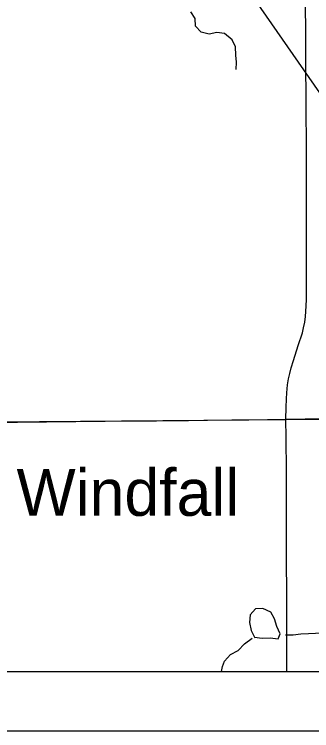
# Model space of a CAD drawing. Extents: x 0 to 34, y 0 to 22.
# Drawn here: x 2.893 to 3.395, y 14 to 15.21 of the extents above; entities that cross this region are included whole.
import ezdxf

# ---------------------------------------------------------------- set-up
doc = ezdxf.new("R2010")
doc.units = 0
for name, color, linetype in [('GM_X_Corporation', 7, 'Continuous'), ('GM_X_Minor_Lake', 7, 'Continuous'), ('GM_X_Minor_River', 7, 'Continuous'), ('GM_X_State_Route', 7, 'Continuous'), ('GM_X_Township_Road', 7, 'Continuous'), ('GM_X_Unincorporated_Text', 7, 'Continuous'), ('SH_Data', 7, 'Continuous'), ('SH_Text', 7, 'Continuous')]:
    doc.layers.add(name, color=color, linetype=linetype)

msp = doc.modelspace()

# ---------------------------------------------------------------- linework, layer by layer
at = {"layer": 'GM_X_Corporation'}
for points in [[(2.1, 20.9), (2.1, 14.1), (7.9734, 14.1), (7.9726, 14.5453), (7.9765, 15.2637), (7.9792, 15.5481), (7.979, 15.5988), (7.9808, 15.7192), (7.9807, 15.9078), (7.9821, 16.2487), (7.9825, 16.3395), (7.9818, 16.3982), (7.9825, 16.6077), (7.9838, 16.7968), (7.9877, 17.3871), (7.9891, 17.5498), (7.991, 17.7727), (7.9901, 18.1613)], [(3.735, 14.5275), (3.3839, 14.5264), (3.3511, 14.525), (2.8655, 14.5214), (2.8502, 15.8768), (2.8488, 16.2), (2.8487, 16.2273), (2.8487, 16.232), (2.8477, 16.3135), (2.8476, 16.3157), (2.8477, 16.7834), (2.837, 17.9259), (2.8293, 18.7154)]]:
    msp.add_lwpolyline(points, dxfattribs=at)
msp.add_lwpolyline([(2.8649, 14.1), (7.9734, 14.1), (7.9726, 14.5453), (7.0871, 14.5429), (7.0197, 14.5427), (6.4941, 14.5412), (6.1476, 14.5397), (5.4644, 14.5374), (4.5212, 14.531), (4.3772, 14.5296), (4.3422, 14.5307), (3.735, 14.5275), (3.3839, 14.5264), (3.3511, 14.525), (2.8655, 14.5214), (2.8638, 14.4461)], close=True, dxfattribs=at)
at = {"layer": 'GM_X_Minor_Lake'}
for points in [[(3.338, 14.155), (3.3416, 14.1638), (3.3361, 14.1762), (3.3321, 14.1887), (3.3259, 14.2003), (3.3121, 14.2065), (3.3, 14.2059), (3.2908, 14.1955), (3.2895, 14.1826), (3.2924, 14.169), (3.2984, 14.1581)], [(3.338, 14.155), (3.3416, 14.1638), (3.3361, 14.1762), (3.3321, 14.1887), (3.3259, 14.2003), (3.3121, 14.2065), (3.3, 14.2059), (3.2908, 14.1955), (3.2895, 14.1826), (3.2924, 14.169), (3.299, 14.157)], [(3.2982, 14.1581), (3.3111, 14.1564), (3.3247, 14.1566), (3.338, 14.155)], [(3.2984, 14.1581), (3.3111, 14.1564), (3.3247, 14.1566), (3.338, 14.155)]]:
    msp.add_lwpolyline(points, dxfattribs=at)
at = {"layer": 'GM_X_Minor_River'}
for points in [[(3.267, 15.1169), (3.2679, 15.1294), (3.2669, 15.1415), (3.266, 15.1552), (3.2604, 15.1672), (3.2474, 15.178), (3.2345, 15.1797), (3.2217, 15.1768), (3.208, 15.18), (3.1988, 15.1904), (3.1982, 15.2033), (3.1908, 15.2146)], [(3.5474, 14.1), (3.5468, 14.112), (3.5375, 14.1232), (3.5283, 14.1336), (3.5231, 14.1472), (3.5221, 14.1601), (3.5151, 14.1717), (3.5033, 14.1753), (3.4905, 14.1713), (3.4781, 14.1692), (3.4652, 14.1678), (3.4528, 14.1672), (3.4399, 14.1659), (3.4267, 14.1656), (3.4146, 14.1647), (3.4014, 14.1644), (3.3893, 14.1638), (3.3764, 14.1632), (3.3636, 14.1615), (3.3504, 14.1616)], [(3.2427, 14.1), (3.2443, 14.1082), (3.2475, 14.1177), (3.2579, 14.1285), (3.2706, 14.1352), (3.2814, 14.1468), (3.2945, 14.1565)]]:
    msp.add_lwpolyline(points, dxfattribs=at)
at = {"layer": 'GM_X_State_Route'}
for points in [[(2.8484, 14.5208), (3.0461, 14.5227), (3.1328, 14.5236), (3.1869, 14.5242), (3.219, 14.5246), (3.2602, 14.525), (3.2885, 14.5253), (3.3512, 14.5262)], [(3.3512, 14.5262), (3.3859, 14.5264), (3.4315, 14.5266)]]:
    msp.add_lwpolyline(points, dxfattribs=at)
at = {"layer": 'GM_X_Township_Road'}
for points in [[(3.3859, 14.7522), (3.386, 14.7652), (3.3862, 14.8038), (3.3861, 14.8471), (3.3859, 14.8828), (3.3858, 14.9178), (3.3857, 14.9945), (3.3854, 15.0448), (3.3848, 15.1479), (3.3846, 15.1851), (3.3845, 15.2218), (3.3846, 15.2555), (3.3848, 15.2929), (3.385, 15.3306), (3.3855, 15.3668), (3.3856, 15.4337), (3.386, 15.4882), (3.3863, 15.5254), (3.3865, 15.5476), (3.3866, 15.5839)], [(3.3512, 14.5262), (3.3515, 14.5463), (3.3521, 14.5609), (3.3526, 14.5709), (3.3541, 14.5846), (3.3557, 14.5945), (3.3577, 14.6037), (3.3603, 14.6132), (3.364, 14.6255), (3.372, 14.6506), (3.3791, 14.6723), (3.3811, 14.6806), (3.3829, 14.6902), (3.3842, 14.6997), (3.3848, 14.708), (3.3857, 14.728), (3.3859, 14.7522)], [(3.3514, 14.5065), (3.3513, 14.5145), (3.3512, 14.5262)], [(3.3527, 14.1), (3.3527, 14.111), (3.3529, 14.1484), (3.3526, 14.2419), (3.3524, 14.2772), (3.3522, 14.3028), (3.3521, 14.4457), (3.3516, 14.4876), (3.3514, 14.5065)]]:
    msp.add_lwpolyline(points, dxfattribs=at)
at = {"layer": 'SH_Data'}
for p, q in [((2.1, 14.1), (8.9, 14.1)), ((2, 14), (9, 14))]:
    msp.add_line(p, q, dxfattribs=at)
at = {"layer": 'SH_Text'}
msp.add_lwpolyline([(3.4887, 15.4514), (2.7956, 15.9593), (3.4887, 14.9614)], close=True, dxfattribs=at)

# ---------------------------------------------------------------- texts
at = {"layer": 'GM_X_Unincorporated_Text'}
msp.add_text('Windfall', height=0.07898, rotation=0, dxfattribs=at).set_placement((2.8968, 14.363))

doc.saveas('drawing.dxf')
